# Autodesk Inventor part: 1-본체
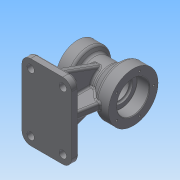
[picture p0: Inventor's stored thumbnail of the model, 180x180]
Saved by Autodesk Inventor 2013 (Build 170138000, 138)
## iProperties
Created: 2015-08
Part Number: 1-본체
Material: 일반
Document SubType Name: Modeling
Designer: Administrator
Density: 1 g/cm^3
Author: Administrator
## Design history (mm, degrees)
sketch "스케치1"
  geometry: L1 (-45, 0)-(45, 0); L2 (-45, 0)-(-45, 35); L3 (-45, 35)-(-25, 35); L4 (-25, 35)-(-19.804, 26); L5 (-19.804, 26)-(8.315, 26); L6 (8.315, 26)-(25, 40); L7 (25, 40)-(45, 40); L8 (45, 40)-(45, 0); 2 further points
  constraints: 16 end point, 3 parallel, 2 perpendicular, 1 coincident, 1 horizontal, 1 midpoint
  dimensions: "d0" = 90 distance of L1.start L1.end; "d1" = 70 diameter of L3 L1; "d2" = 80 diameter of L7 L1; "d3" = 52 diameter of L5 L1; "d4" = 60 deg angle of L5 L4; "d5" = 40 deg angle of L5 L6; "d6" = 20 distance of L2.end L3.end; "d7" = 20 distance of L6.end L7.end
revolve "회전1" sketch "스케치1" stored, may be unused: angle "d8" = 90 deg
node "작업 평면1"
sketch "스케치4"
  geometry: L1 (35, -78)-(-45, -78); L2 (-45, -78)-(-45, -90); L3 (-45, -90)-(35, -90); L4 (35, -90)-(35, -78); L5 (35, -78)-(-45, -90); L6 (-45, -78)-(35, -90); L7 (-45, -35)-(-45, 35) reference; L8 (-45, 35)-(-25, 35) reference; L9 (-25, 35)-(-19.804, 26) reference; L10 (-19.804, 26)-(8.315, 26) reference; L11 (8.315, 26)-(25, 40) reference; L12 (25, 40)-(45, 40) reference; L13 (45, 40)-(45, -40) reference; L14 (45, -40)-(25, -40) reference; L15 (25, -40)-(8.315, -26) reference; L16 (8.315, -26)-(-19.804, -26) reference; L17 (-19.804, -26)-(-25, -35) reference; L18 (-25, -35)-(-45, -35) reference; 2 further points
  constraints: 12 end point, 2 midpoint, 2 parallel, 1 horizontal, 1 perpendicular, 1 vertical alignment
  dimensions: "d14" = 12 distance of L1.end L2.end; "d16" = 80 distance of L2.end L3.end; "d17" = 90 distance from line of L3 point (0, 0)
extrude "돌출2" join sketch "스케치4" stored distance "d18" = 122; taper "d19" = 0 deg
node "작업 평면2"
sketch "스케치7"
  geometry: L1 (-122, 0)-(-122, 12) reference; L2 (-122, 12)-(0, 12) reference; L3 (0, 12)-(0, 0) reference; L4 (0, 0)-(-122, 0) reference; L5 (-10, 12)-(-35.909, 83.185); L6 (-112, 12)-(-86.091, 83.185); A1 r 26 centre (-61, 90) between (-35.909, 83.185) and (-86.091, 83.185) reference; 1 further point
  constraints: 4 end point, 2 point on circle, 2 point on line, 1 equal length
  dimensions: "d20" = 10 distance of L1.end L6.start; "d21" = 10 distance of L2.end L5.start; "d22" = 70 deg angle of L2 L6
extrude "돌출3" join sketch "스케치7" stored distance "d23" = 12; taper "d24" = 0 deg
sketch "스케치10"
  geometry: L1 (-45, -35)-(-45, 35) reference; L2 (-45, 35)-(-25, 35) reference; L3 (-25, 35)-(-19.804, 26) reference; L4 (-19.804, 26)-(8.315, 26) reference; L5 (8.315, 26)-(25, 40) reference; L6 (25, 40)-(45, 40) reference; L7 (45, 40)-(45, -40) reference; L8 (45, -40)-(25, -40) reference; L9 (25, -40)-(8.315, -26) reference; L10 (8.315, -26)-(1, -26) reference; L11 (1, -26)-(1, -78) reference; L12 (1, -78)-(35, -78) reference; L13 (35, -78)-(35, -90) reference; L14 (35, -90)-(-45, -90) reference; L15 (-45, -90)-(-45, -78) reference; L16 (-45, -78)-(-11, -78) reference; L17 (-11, -78)-(-11, -26) reference; L18 (-11, -26)-(-19.804, -26) reference; L19 (-19.804, -26)-(-25, -35) reference; L20 (-25, -35)-(-45, -35) reference; L21 (-35, -78)-(-35, -8.917); L22 (-35, -8.917)-(37.181, -8.917); L23 (37.181, -8.917)-(25, -78); 1 further point
  constraints: 6 end point, 2 perpendicular, 2 point on line
  dimensions: "d30" = 10 distance from line of L21.start L15; "d32" = 10 distance from line of L13 L23.end; "d33" = 80 deg angle of L12 L23
extrude "돌출5" join sketch "스케치10" stored distance "d34" = 12; taper "d35" = 0 deg
fillet "모깎기1" dims "d36" = 14
hole "구멍1" diameter "d39" = 38; stored, may be unused: countersink angle "d43" = 90 deg, drill point angle "d45" = 0 deg; dims "d37" = 10, "d38" = 10, "d40" = 6, "d41" = 52, "d42" = 20, "d44" = 23
fillet "모깎기2" dims "d46" = 3
hole "구멍2" diameter "d49" = 32; stored, may be unused: countersink angle "d53" = 90 deg, drill point angle "d55" = 0 deg; dims "d47" = 10, "d48" = 10, "d50" = 6, "d51" = 40, "d52" = 17, "d54" = 23
fillet "모깎기3" dims "d56" = 5, "d57" = 5
fillet "모깎기4" dims "d58" = 0.3
fillet "모깎기5" dims "d59" = 0.3
sketch "스케치13"
  geometry: C1 r 26 at (0, 0) reference; 1 further point
  constraints: 1 vertical alignment
  dimensions: "d60" = 33 distance of point (0, 33) C1.centre
hole "구멍3" sketch "스케치13" at (0, 33) diameter "d61" = 3.242; stored, may be unused: countersink angle "d65" = 90 deg, drill point angle "d67" = 0 deg; dims "d62" = 10, "d63" = 40, "d64" = 17, "d66" = 13
sketch "스케치14"
  geometry: C1 r 20 at (0, 0) reference; 1 further point
  constraints: 1 vertical alignment
  dimensions: "d71" = 27 distance of C1.centre point (0, 27)
hole "구멍4" sketch "스케치14" at (0, 27) diameter "d72" = 3.242; stored, may be unused: countersink angle "d76" = 90 deg, drill point angle "d78" = 0 deg; dims "d73" = 10, "d74" = 40, "d75" = 17, "d77" = 13
sketch "스케치15"
  geometry: C1 r 6 at (0, 14); C2 r 6 at (52, 14); C3 r 6 at (52, 108); C4 r 6 at (0, 108); A1 r 14 centre (0, 108) between (0, 122) and (-14, 108) reference; A2 r 14 centre (0, 14) between (-14, 14) and (0, 0) reference; A3 r 14 centre (52, 14) between (52, 0) and (66, 14) reference; A4 r 14 centre (52, 108) between (66, 108) and (52, 122) reference; 1 further point
  constraints: 4 centre point, 4 coincident
  dimensions: "d82" = 12 diameter of C1; "d83" = 12 diameter of C2; "d84" = 12 diameter of C3; "d85" = 12 diameter of C4
extrude "돌출6" cut sketch "스케치15" stored distance "d86" = 12; taper "d87" = 0 deg
sketch "스케치16"
  geometry: L1 (31, 36)-(31, 30); L2 (43, 36)-(43, 30); L3 (0, 12)-(14, 12) reference; A1 r 26 centre (61, 90) between (35.909, 83.185) and (55, 64.702) reference; A2 r 6 centre (37, 36) between (43, 36) and (31, 36); A3 r 6 centre (37, 30) between (31, 30) and (43, 30)
  constraints: 4 end point, 4 point on circle, 4 tangent, 2 centre point, 1 vertical alignment
  dimensions: "d88" = 12 diameter of A2; "d89" = 12 diameter of A3; "d90" = 18 dimension on A3 A2; "d91" = 24 horizontal distance of A1.centre A2.centre; "d92" = 18 distance from line of L3 A3.centre
extrude "돌출7" cut sketch "스케치16" stored distance "d93" = 12; taper "d94" = 0 deg
fillet "모깎기6" dims "d95" = 3
fillet "모깎기7" dims "d96" = 3
fillet "모깎기8" dims "d97" = 3
fillet "모깎기9" dims "d98" = 3
chamfer "모따기1" distance "d99" = 1; stored, may be unused: second distance "d100" = 2, angle "d101" = 45 deg
fillet "모깎기10" dims "d102" = 3
sketch "스케치18"
  geometry: L1 (-42, -78)-(-31, -78) reference; L2 (-35, -37.881)-(-35, -75) reference; 2 further points
  constraints: 1 other
  dimensions: "d105" = 24 distance from line of point (-19, -54) L1; "d106" = 16 distance from line of point (-19, -54) L2
feature "엠보싱1" sketch "스케치18" dims "d0" = 90, "d1" = 70, "d2" = 80, "d3" = 52, "d4" = 60 deg, "d5" = 40 deg, "d6" = 20, "d7" = 20, "d107" = 0.5, "d108" = 0
node "솔리드1"
pattern_circular "원형 패턴1" dims angle "d69" = 360 deg
pattern_circular "원형 패턴2" dims angle "d80" = 360 deg
mirror "대칭1"
node "절단 모서리 투영1"
node "절단 모서리 투영2"
node "절단 모서리 투영4"
